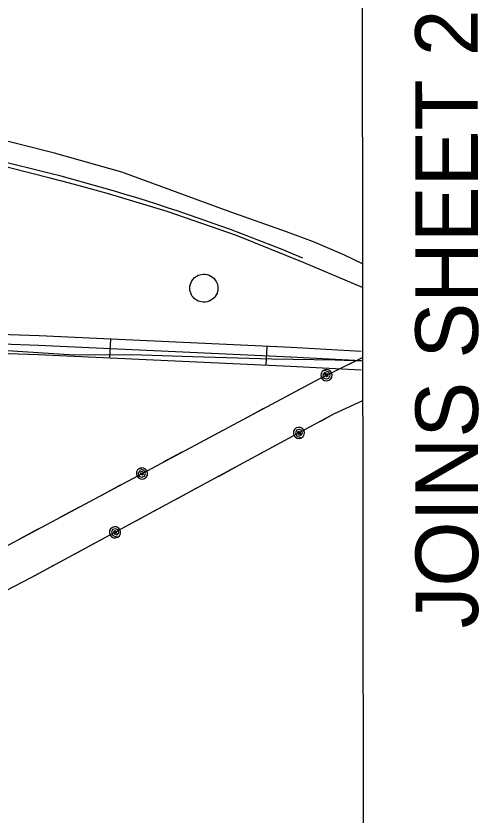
# Model space of a CAD drawing. Extents: x 3281947 to 3319794, y 715894 to 741249.
# Drawn here: x 3317026 to 3317766, y 723317 to 724593 of the extents above; entities that cross this region are included whole.
import ezdxf

# ---------------------------------------------------------------- set-up
doc = ezdxf.new("R2010")
doc.units = 0
for name, color, linetype in [('V-ANNO-TEXT', 7, 'Continuous'), ('V-DOMW-TANK', 7, 'Continuous'), ('V-DTCH-CNTR', 7, 'Continuous'), ('V-GRID-FRAM', 7, 'Continuous'), ('V-RAIL-TRAK', 7, 'Continuous'), ('V-ROAD-CNTR', 7, 'Continuous'), ('V-TOPO-SHOR', 7, 'Continuous'), ('V-UTIL-LINE', 7, 'Continuous')]:
    doc.layers.add(name, color=color, linetype=linetype)

msp = doc.modelspace()

# ---------------------------------------------------------------- linework, layer by layer
at = {"layer": 'V-DOMW-TANK'}
msp.add_lwpolyline([(3317349.1, 724158.5), (3317348.9, 724156.1), (3317348.5, 724153.4), (3317347.7, 724150.8), (3317346.5, 724148.1), (3317344.9, 724145.5), (3317342.9, 724143.1), (3317340.6, 724141), (3317337.9, 724139.2), (3317335, 724137.7), (3317331.9, 724136.8), (3317328.9, 724136.3), (3317325.8, 724136.2), (3317322.9, 724136.5), (3317320.2, 724137.1), (3317317.7, 724138), (3317315.5, 724139.2), (3317313.4, 724140.5), (3317311.4, 724142.2), (3317309.5, 724144.2), (3317307.7, 724146.6), (3317306.3, 724149.3), (3317305.2, 724152.2), (3317304.5, 724155.3), (3317304.3, 724158.5), (3317304.5, 724161.8), (3317305.2, 724164.9), (3317306.3, 724167.8), (3317307.7, 724170.5), (3317309.5, 724172.9), (3317311.4, 724174.9), (3317313.4, 724176.6), (3317315.5, 724177.9), (3317317.7, 724179.1), (3317320.2, 724180), (3317322.9, 724180.6), (3317325.8, 724180.9), (3317328.9, 724180.8), (3317331.9, 724180.3), (3317335, 724179.4), (3317337.9, 724177.9), (3317340.6, 724176.1), (3317342.9, 724174), (3317344.9, 724171.6), (3317346.5, 724169), (3317347.7, 724166.3), (3317348.5, 724163.7), (3317348.9, 724161)], close=True, dxfattribs=at)
at = {"layer": 'V-DTCH-CNTR'}
msp.add_lwpolyline([(3316862.6, 724064.5), (3316920.4, 724063.6), (3317020.8, 724058.6), (3317119.2, 724052.1), (3317211.5, 724052.6), (3317308.5, 724049.6), (3317435.1, 724045.8), (3317536.3, 724044.1), (3317580.3, 724042.5)], dxfattribs=at)
at = {"layer": 'V-GRID-FRAM'}
msp.add_lwpolyline([(3286080.7, 739456.2), (3317564.6, 739474.5), (3317583.1, 721289.3), (3286083.3, 721271), (3286080.7, 739456.2)], dxfattribs=at)
at = {"layer": 'V-RAIL-TRAK'}
msp.add_lwpolyline([(3317580.2, 724159.9), (3317486.8, 724199.3), (3317378.6, 724242.9), (3317267.8, 724281.2), (3317174.4, 724309.4), (3317143.3, 724318), (3317112.1, 724326.4), (3317080.9, 724334.5), (3317049.6, 724342.4), (3317018.2, 724350.1), (3316986.8, 724357.6), (3316955.4, 724364.9), (3316926.8, 724370.2), (3316898.1, 724375.2), (3316869.3, 724380.1), (3316840.6, 724384.7), (3316811.8, 724389.1), (3316722.6, 724401.4), (3316590.1, 724416.1), (3316473.9, 724423.2), (3316337.1, 724429.4), (3316243.1, 724434.4), (3316103.7, 724438.4), (3315941.1, 724444.7)], dxfattribs=at)
at = {"layer": 'V-ROAD-CNTR'}
for p, q in [((3317176.6, 724046.9), (3317178, 724076.9)), ((3317426.3, 724035.4), (3317427.7, 724065.3))]:
    msp.add_line(p, q, dxfattribs=at)
for points in [[(3317577.9, 724057.7), (3317466.4, 724063.6), (3317063.2, 724082.2), (3316888.5, 724088.1)], [(3317577.9, 724042.7), (3317465.6, 724048.6), (3317062.6, 724067.2), (3316887.5, 724073.2)], [(3317578, 724027.7), (3317464.9, 724033.6), (3317062, 724052.2), (3316886.4, 724058.2)]]:
    msp.add_lwpolyline(points, dxfattribs=at)
msp.add_arc((3316336.1, 721445.7), 2990.4, 67.411, 78.2917, dxfattribs=at)
at = {"layer": 'V-TOPO-SHOR'}
msp.add_lwpolyline([(3317580.1, 724197.6), (3317550.5, 724211.8), (3317501.9, 724232.8), (3317458.9, 724248.8), (3317365.3, 724281.7), (3317195.4, 724343.9), (3317087.8, 724374.1), (3316981.7, 724400.7), (3316933.1, 724411.3), (3316926.9, 724418.2)], dxfattribs=at)
at = {"layer": 'V-UTIL-LINE'}
for points in [[(3312325.9, 721286.3), (3312568.6, 721404.8), (3313073.1, 721661.4), (3313565.8, 721918.7), (3314062.8, 722182.3), (3314555.8, 722442), (3315054, 722700.8), (3315538, 722975.8), (3316036.6, 723234.9), (3316539, 723494.9), (3317512.1, 724014.4), (3317580.3, 724047.8)], [(3317557.6, 724036.7), (3317580.3, 724047.8)], [(3317580.3, 724047.8), (3317580.3, 724047.8)], [(3317580.3, 724047.8), (3317580.3, 724047.8)], [(3317522.6, 724019.6), (3317520.1, 724021), (3317520.3, 724018.7), (3317522.8, 724017.4), (3317525.2, 724018.9), (3317523.9, 724022.1), (3317519.5, 724023.7), (3317516.8, 724020.4), (3317517.7, 724015.6), (3317521.9, 724013.9), (3317526.3, 724015), (3317528.3, 724019.3), (3317526.2, 724024.4), (3317518.7, 724027.6), (3317515.9, 724025.5), (3317514.1, 724022.5), (3317513.6, 724019), (3317514.5, 724015.6), (3317516.7, 724012.8), (3317519.7, 724011.1), (3317523.2, 724010.6), (3317526.6, 724011.5), (3317529.4, 724013.6), (3317531.1, 724016.6), (3317531.6, 724020.1), (3317530.7, 724023.5), (3317528.6, 724026.3), (3317525.5, 724028.1), (3317522.1, 724028.5), (3317518.7, 724027.6)], [(3317458, 723985.6), (3317488, 724001.6)], [(3317580.3, 723978.6), (3317533.6, 723957.1), (3317050.3, 723696.1), (3316565.9, 723444.6), (3316061.4, 723180), (3315565.9, 722917.4), (3315061.3, 722652.1), (3314571.2, 722391.1), (3314064.2, 722130), (3313579.5, 721870.9), (3313085.3, 721607), (3312590.5, 721349.4), (3312466.8, 721286.3)], [(3317580.3, 723978.6), (3317579.5, 723978.2)], [(3317580.3, 723978.6), (3317580.3, 723978.6)], [(3317580.3, 723978.6), (3317580.3, 723978.6)], [(3317392.7, 723950.7), (3317422.7, 723966.7)], [(3317543.1, 723961.5), (3317533.6, 723957.1), (3317512.9, 723945.9)], [(3317327.5, 723915.8), (3317357.5, 723931.9)], [(3317478.6, 723927.4), (3317481.2, 723926.1), (3317480.9, 723928.4), (3317478.4, 723929.6), (3317476, 723927.9), (3317477.4, 723924.8), (3317481.9, 723923.4), (3317484.5, 723926.8), (3317483.4, 723931.5), (3317479.1, 723933.1), (3317474.8, 723931.8), (3317472.9, 723927.4), (3317475.3, 723922.4), (3317482.9, 723919.5), (3317485.6, 723921.7), (3317487.2, 723924.8), (3317487.6, 723928.3), (3317486.5, 723931.7), (3317484.3, 723934.4), (3317481.2, 723936), (3317477.7, 723936.3), (3317474.3, 723935.3), (3317471.6, 723933.1), (3317470, 723930), (3317469.7, 723926.5), (3317470.7, 723923.1), (3317472.9, 723920.4), (3317476, 723918.8), (3317479.5, 723918.4), (3317482.9, 723919.5)], [(3317444.3, 723908.9), (3317414.4, 723892.7)], [(3317262.2, 723881), (3317292.2, 723897)], [(3317227.8, 723862.6), (3317225.2, 723863.9), (3317225.5, 723861.6), (3317228, 723860.4), (3317230.4, 723862.1), (3317229, 723865.2), (3317224.5, 723866.6), (3317221.9, 723863.2), (3317223, 723858.5), (3317227.3, 723857), (3317231.6, 723858.2), (3317233.5, 723862.6), (3317231.2, 723867.6), (3317223.6, 723870.6), (3317220.8, 723868.3), (3317219.2, 723865.2), (3317218.8, 723861.8), (3317219.9, 723858.4), (3317222.1, 723855.7), (3317225.2, 723854), (3317228.7, 723853.7), (3317232, 723854.7), (3317234.7, 723856.9), (3317236.4, 723860), (3317236.7, 723863.5), (3317235.7, 723866.9), (3317233.5, 723869.6), (3317230.4, 723871.2), (3317226.9, 723871.6), (3317223.6, 723870.6)], [(3317379.2, 723873.7), (3317349.3, 723857.5)], [(3317163.4, 723828.2), (3317193.4, 723844.3)], [(3317314.1, 723838.5), (3317284.2, 723822.4)], [(3317098.1, 723793.4), (3317128.1, 723809.4)], [(3317249, 723803.4), (3317219, 723787.2)], [(3317184.7, 723768.7), (3317187.3, 723767.4), (3317187, 723769.7), (3317184.5, 723770.9), (3317182.1, 723769.2), (3317183.6, 723766.1), (3317188, 723764.7), (3317190.6, 723768.1), (3317189.5, 723772.8), (3317185.2, 723774.4), (3317180.9, 723773.1), (3317179.1, 723768.7), (3317181.4, 723763.7), (3317189, 723760.8), (3317191.7, 723763), (3317193.4, 723766.1), (3317193.7, 723769.6), (3317192.6, 723773), (3317190.4, 723775.7), (3317187.3, 723777.3), (3317183.8, 723777.6), (3317180.5, 723776.6), (3317177.7, 723774.4), (3317176.1, 723771.3), (3317175.8, 723767.8), (3317176.8, 723764.4), (3317179.1, 723761.7), (3317182.2, 723760.1), (3317185.7, 723759.7), (3317189, 723760.8)], [(3317032.8, 723758.5), (3317062.8, 723774.6)], [(3317150.4, 723750.1), (3317120.5, 723734)], [(3317085.3, 723715), (3317055.4, 723698.8)]]:
    msp.add_lwpolyline(points, dxfattribs=at)

# ---------------------------------------------------------------- texts
at = {"layer": 'V-ANNO-TEXT'}
msp.add_text('JOINS SHEET 25', height=100, rotation=90.0333, dxfattribs=at).set_placement((3317765, 723615.2))

doc.saveas('drawing.dxf')
